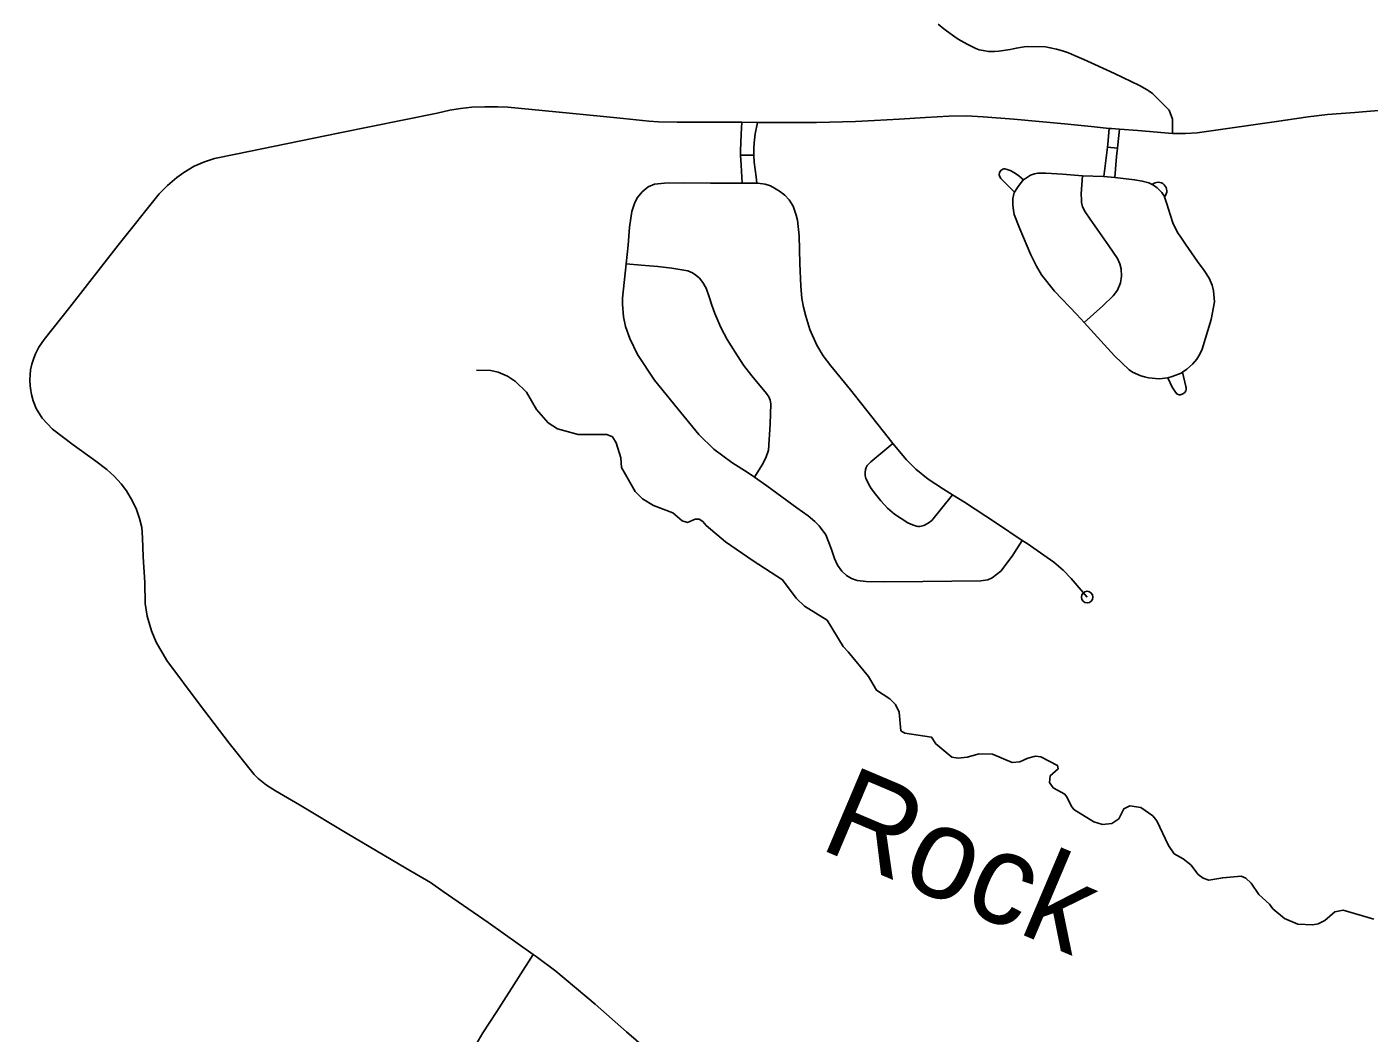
# Model space of a CAD drawing. Extents: x -19 to 366, y -4 to 359.
# Drawn here: x 142.275 to 143.458, y 193.183 to 194.069 of the extents above; entities that cross this region are included whole.
import ezdxf

# ---------------------------------------------------------------- set-up
doc = ezdxf.new("R2010")
doc.units = 0
for name, color, linetype in [('Level 32', 7, 'Continuous'), ('Level 33', 7, 'Continuous'), ('Level 34', 7, 'Continuous'), ('Level 35', 7, 'Continuous'), ('Level 60', 7, 'Continuous')]:
    doc.layers.add(name, color=color, linetype=linetype)

msp = doc.modelspace()

# ---------------------------------------------------------------- linework, layer by layer
at = {"layer": 'Level 32'}
msp.add_lwpolyline([(143.2733, 194.0043), (143.2725, 194.0053), (143.2699, 194.008), (143.2671, 194.0104), (143.2642, 194.0126), (143.2624, 194.0137), (143.2556, 194.0177), (143.2336, 194.0281), (143.2162, 194.0361), (143.2066, 194.0405), (143.1985, 194.0441), (143.1932, 194.0462), (143.1879, 194.048), (143.1825, 194.0496), (143.177, 194.0508), (143.173, 194.0516), (143.1569, 194.052), (143.1541, 194.0516), (143.1506, 194.0511), (143.1473, 194.0505), (143.1445, 194.0499), (143.1418, 194.0493), (143.1319, 194.0477), (143.1279, 194.0475), (143.1228, 194.0475), (143.1181, 194.0483), (143.1145, 194.0491), (143.1115, 194.0501), (143.1067, 194.0524), (143.104, 194.0539), (143.0959, 194.0585), (143.0929, 194.0604), (143.0857, 194.0658), (143.0834, 194.0675), (143.0782, 194.0717)], dxfattribs=at)
at = {"layer": 'Level 33'}
for p, q in [((142.9043, 193.9562), (142.9159, 193.9562)), ((143.2276, 193.9633), (143.2364, 193.9625)), ((142.8034, 193.8604), (142.8052, 193.8768)), ((142.8001, 193.8303), (142.8034, 193.8604)), ((143.0189, 193.686), (143.0385, 193.7023)), ((143.0727, 193.6344), (143.091, 193.657))]:
    msp.add_line(p, q, dxfattribs=at)
for points in [[(143.2848, 193.9752), (143.2962, 193.9752), (143.3065, 193.976), (143.3764, 193.9858), (143.4042, 193.99), (143.4212, 193.9921), (143.4455, 193.9938), (143.4694, 193.9957), (143.4884, 193.9971), (143.5084, 193.9987), (143.5217, 194.0017), (143.5469, 194.0079), (143.5711, 194.0132), (143.5843, 194.0154), (143.5968, 194.0164), (143.608, 194.0172), (143.6204, 194.0177), (143.6361, 194.0167), (143.6637, 194.0127), (143.6699, 194.0116)], [(142.8853, 193.9853), (142.8485, 193.9854), (142.8319, 193.9855), (142.8233, 193.9862), (142.8012, 193.9885), (142.7835, 193.9903), (142.7414, 193.9943), (142.6992, 193.9984), (142.6904, 193.9987), (142.6789, 193.9988), (142.6674, 193.9985), (142.6576, 193.9973), (142.648, 193.9957), (142.6368, 193.9933), (142.5498, 193.9755), (142.4595, 193.9572), (142.4406, 193.9532), (142.4319, 193.9503), (142.4229, 193.9464), (142.4136, 193.941), (142.4074, 193.9364), (142.3993, 193.9295), (142.3919, 193.9221), (142.3559, 193.8769), (142.3133, 193.8223), (142.2906, 193.7937), (142.286, 193.7872), (142.2829, 193.7812), (142.2816, 193.7773), (142.2797, 193.772), (142.2787, 193.7672), (142.2782, 193.7626), (142.278, 193.758), (142.2782, 193.7529), (142.2788, 193.749), (142.2795, 193.7453), (142.2811, 193.7397), (142.2836, 193.7329), (142.2888, 193.7246), (142.2981, 193.7148), (142.3163, 193.7011), (142.3361, 193.6865), (142.3459, 193.6792), (142.3524, 193.6733), (142.3584, 193.6667), (142.3631, 193.6604), (142.3686, 193.6513), (142.3719, 193.6441), (142.3746, 193.6362), (142.3766, 193.6281), (142.3774, 193.6191), (142.378, 193.6025), (142.3792, 193.5799), (142.3797, 193.5612), (142.3814, 193.5502), (142.3853, 193.5371), (142.3893, 193.5271), (142.3987, 193.511), (142.4273, 193.4728), (142.4537, 193.4383), (142.4756, 193.4106), (142.4793, 193.407), (142.4865, 193.4013), (142.4945, 193.3961), (142.5156, 193.3838), (142.5575, 193.3588), (142.6092, 193.3282), (142.6309, 193.3154), (142.6423, 193.3076), (142.6817, 193.2803), (142.7216, 193.2522)], [(143.1895, 193.9838), (143.1674, 193.9857), (143.145, 193.9878), (143.1181, 193.9901), (143.103, 193.9907), (143.0878, 193.9905), (143.0671, 193.9895), (143.0439, 193.9878), (143.0222, 193.9867), (143.0055, 193.9858), (142.9711, 193.9849), (142.919, 193.9851)], [(142.9054, 193.9852), (142.8853, 193.9853)], [(142.9043, 193.9562), (142.9041, 193.9601), (142.9046, 193.9746), (142.9054, 193.9852)], [(142.919, 193.9851), (142.9054, 193.9852)], [(142.919, 193.9851), (142.9171, 193.975), (142.9162, 193.9671), (142.916, 193.9621), (142.9159, 193.9562)], [(143.229, 193.9798), (143.2132, 193.9814), (143.1895, 193.9838)], [(143.229, 193.9798), (143.2279, 193.966), (143.2276, 193.9633)], [(143.2381, 193.9791), (143.2311, 193.9796), (143.229, 193.9798)], [(143.2381, 193.9791), (143.2367, 193.9653), (143.2364, 193.9625)], [(143.2849, 193.9752), (143.2542, 193.9778), (143.2381, 193.9791)], [(142.9056, 193.9314), (142.9048, 193.9473), (142.9043, 193.9562)], [(142.9159, 193.9562), (142.9159, 193.9562), (142.9162, 193.95), (142.9179, 193.937), (142.9184, 193.9314)], [(143.2276, 193.9633), (143.2244, 193.9373)], [(143.2364, 193.9625), (143.2355, 193.955), (143.2341, 193.9366)], [(143.1457, 193.9237), (143.1334, 193.9357), (143.1326, 193.9371), (143.1322, 193.9389), (143.1323, 193.9408), (143.1334, 193.9427), (143.1343, 193.9434), (143.1352, 193.944), (143.1361, 193.9442), (143.1371, 193.9442), (143.1391, 193.9437), (143.1418, 193.9428), (143.1456, 193.9405), (143.1493, 193.938), (143.1534, 193.9346)], [(142.8052, 193.8768), (142.8064, 193.8928), (142.8083, 193.9065), (142.811, 193.9145), (142.8135, 193.9188), (142.8174, 193.9238), (142.8227, 193.9282), (142.8285, 193.9305), (142.8373, 193.9314), (142.8542, 193.9319), (142.8777, 193.9314), (142.9056, 193.9314)], [(142.9056, 193.9314), (142.9184, 193.9314)], [(142.9184, 193.9314), (142.9193, 193.9314), (142.9258, 193.9306), (142.9305, 193.9291), (142.9341, 193.9272), (142.9385, 193.9244), (142.9431, 193.9209), (142.947, 193.9168), (142.9505, 193.9113), (142.9532, 193.9033), (142.9545, 193.899), (142.9557, 193.885), (142.9565, 193.8608), (142.9573, 193.8409), (142.9582, 193.83), (142.9597, 193.8223), (142.9618, 193.8143), (142.9653, 193.8027), (142.9713, 193.7887), (142.9769, 193.7795), (142.9836, 193.7706), (143.0012, 193.7496), (143.0343, 193.7074), (143.0385, 193.7023)], [(143.1457, 193.9237), (143.1481, 193.9278), (143.1532, 193.9345), (143.1534, 193.9346)], [(143.1534, 193.9346), (143.1596, 193.9386), (143.1631, 193.9396), (143.1662, 193.9402), (143.1732, 193.9403), (143.1878, 193.9395)], [(143.1878, 193.9395), (143.2054, 193.9381)], [(143.2068, 193.8089), (143.2234, 193.8236), (143.2326, 193.8322), (143.2364, 193.8373), (143.2389, 193.8437), (143.2399, 193.8495), (143.2396, 193.856), (143.2385, 193.8605), (143.2362, 193.8652), (143.2287, 193.8762), (143.2122, 193.8997), (143.2078, 193.9063), (143.2056, 193.9107), (143.2047, 193.9146), (143.2045, 193.9168), (143.2044, 193.922), (143.2054, 193.9381)], [(143.2054, 193.9381), (143.2241, 193.9373), (143.2244, 193.9373)], [(143.2244, 193.9373), (143.2341, 193.9366)], [(143.2341, 193.9366), (143.2514, 193.9345), (143.2581, 193.9333), (143.2639, 193.9317), (143.2669, 193.9304)], [(143.1504, 193.8913), (143.1453, 193.9039), (143.1446, 193.9077), (143.144, 193.912), (143.1442, 193.9181), (143.1453, 193.9232), (143.1457, 193.9237)], [(143.2669, 193.9304), (143.268, 193.9299), (143.2714, 193.9275), (143.2753, 193.9234), (143.2778, 193.9197), (143.2778, 193.9196)], [(143.2778, 193.9196), (143.2799, 193.9132), (143.2826, 193.9039), (143.2855, 193.8957), (143.2899, 193.8872), (143.2914, 193.8847)], [(143.2068, 193.8089), (143.2004, 193.8159), (143.1808, 193.8365), (143.1693, 193.8509), (143.165, 193.8585), (143.1601, 193.8683), (143.1504, 193.8913)], [(143.3219, 193.827), (143.321, 193.8366), (143.3196, 193.8418), (143.317, 193.8478), (143.3127, 193.8546), (143.3069, 193.8624), (143.2961, 193.8777), (143.2914, 193.8847)], [(142.9164, 193.6725), (142.9233, 193.6833), (142.9266, 193.6896), (142.9289, 193.6962), (142.9303, 193.7191), (142.931, 193.7372), (142.9304, 193.7405), (142.9291, 193.7434), (142.9271, 193.7463), (142.914, 193.7617), (142.9068, 193.7711), (142.8995, 193.7827), (142.8924, 193.7938), (142.8867, 193.8044), (142.8815, 193.8168), (142.8789, 193.8241), (142.8765, 193.8315), (142.8739, 193.8391), (142.871, 193.8439), (142.8679, 193.8479), (142.8649, 193.8505), (142.8618, 193.8526), (142.8577, 193.8542), (142.8526, 193.8553), (142.8436, 193.8567), (142.8312, 193.8581), (142.8166, 193.8592), (142.8034, 193.8604)], [(142.8001, 193.8303), (142.8003, 193.8249), (142.8012, 193.8139), (142.8029, 193.8053), (142.8066, 193.7948), (142.8133, 193.7807), (142.8284, 193.7581), (142.8489, 193.7327), (142.8675, 193.7101), (142.8808, 193.6972), (142.8966, 193.6855), (142.911, 193.6763), (142.9164, 193.6725)], [(143.3219, 193.827), (143.3187, 193.8115), (143.3108, 193.7854), (143.309, 193.7809), (143.3061, 193.7766), (143.3024, 193.7722), (143.2975, 193.7677), (143.2936, 193.7651)], [(143.2466, 193.7672), (143.2338, 193.7793), (143.2216, 193.7927), (143.2068, 193.8089)], [(143.2808, 193.76), (143.2807, 193.76), (143.273, 193.7592), (143.2637, 193.7599), (143.2601, 193.7608), (143.257, 193.7617), (143.2496, 193.7651), (143.2466, 193.7672)], [(143.2936, 193.7651), (143.2923, 193.7642), (143.2844, 193.7611), (143.2808, 193.76)], [(143.2808, 193.76), (143.2846, 193.7518), (143.2873, 193.7474), (143.2885, 193.7459), (143.2892, 193.7456), (143.2906, 193.7452), (143.2918, 193.7452), (143.294, 193.746), (143.2957, 193.7472), (143.2966, 193.7485), (143.2969, 193.7497), (143.2968, 193.7514), (143.2966, 193.7523), (143.2936, 193.7651)], [(143.0385, 193.7023), (143.0505, 193.6878), (143.0585, 193.6797), (143.0696, 193.6709), (143.0831, 193.662), (143.091, 193.657)], [(143.0189, 193.686), (143.0159, 193.6828), (143.015, 193.6811), (143.0143, 193.6792), (143.014, 193.6766), (143.0141, 193.6739), (143.0147, 193.6713), (143.0157, 193.6692), (143.0171, 193.6662), (143.0194, 193.6625), (143.023, 193.6575), (143.0279, 193.6516), (143.0337, 193.6451), (143.0397, 193.6399), (143.0456, 193.6361), (143.0515, 193.6324), (143.0556, 193.6305), (143.0591, 193.6293), (143.0605, 193.6292), (143.0618, 193.6292), (143.0632, 193.6294), (143.0656, 193.63), (143.0696, 193.6319), (143.0727, 193.6344)], [(142.9164, 193.6725), (142.9274, 193.6648), (142.9539, 193.6456), (142.9637, 193.6384), (142.9697, 193.6335), (142.9734, 193.6298), (142.9792, 193.6217), (142.9821, 193.615), (142.9843, 193.6088), (142.987, 193.601), (142.9896, 193.595), (142.9933, 193.5898), (142.9976, 193.5858), (143.0019, 193.5832), (143.0068, 193.5816), (143.0148, 193.5805), (143.0307, 193.5803), (143.0647, 193.5806), (143.1158, 193.5812), (143.1221, 193.5821), (143.126, 193.5839), (143.1336, 193.5897), (143.1434, 193.603), (143.1523, 193.6168)], [(143.091, 193.657), (143.1014, 193.6504), (143.1296, 193.632), (143.1523, 193.6168)], [(143.1523, 193.6168), (143.1566, 193.614), (143.1802, 193.5978)], [(143.2097, 193.5668), (143.2043, 193.5731), (143.1954, 193.5833), (143.1883, 193.5907), (143.1802, 193.5978)], [(142.6048, 193.0965), (142.609, 193.103), (142.6124, 193.1081), (142.6163, 193.1142), (142.6192, 193.1185), (142.6246, 193.124), (142.6429, 193.141), (142.6552, 193.1521), (142.662, 193.1591), (142.6664, 193.1646), (142.6729, 193.176), (142.6771, 193.1831), (142.6895, 193.202), (142.7087, 193.2319), (142.7216, 193.2522)], [(142.7216, 193.2522), (142.7242, 193.2504), (142.7414, 193.2374), (142.776, 193.2082), (142.8037, 193.184), (142.8313, 193.1601)]]:
    msp.add_lwpolyline(points, dxfattribs=at)
msp.add_circle((143.2096, 193.5669), 0.00509, dxfattribs=at)
msp.add_arc((143.2721, 193.9247), 0.00765, 318.0474, 132.7124, dxfattribs=at)
at = {"layer": 'Level 34'}
msp.add_lwpolyline([(143.2848, 193.9752), (143.2848, 193.988), (143.2818, 193.9959), (143.2733, 194.0043)], dxfattribs=at)
at = {"layer": 'Level 35'}
for points in [[(142.8677, 193.6356), (142.8643, 193.6356), (142.8575, 193.6327), (142.8529, 193.6342), (142.8445, 193.6411), (142.8274, 193.6476), (142.8179, 193.6534), (142.8114, 193.66), (142.7993, 193.6811), (142.7986, 193.6896), (142.7947, 193.7027), (142.7913, 193.7082), (142.7863, 193.71), (142.7611, 193.71), (142.7429, 193.7152), (142.7347, 193.7204), (142.7244, 193.7321), (142.7155, 193.7474), (142.706, 193.7568), (142.6989, 193.7615), (142.6907, 193.765), (142.6841, 193.7666), (142.6716, 193.7667)], [(143.3074, 193.3226), (143.3008, 193.331), (143.2943, 193.3363), (143.2863, 193.3408), (143.2812, 193.3481), (143.2711, 193.3697), (143.2675, 193.3742), (143.257, 193.3815), (143.2473, 193.3831), (143.242, 193.3804), (143.2374, 193.3715), (143.2312, 193.3676), (143.2232, 193.3666), (143.2154, 193.369), (143.1979, 193.3799), (143.1954, 193.3829), (143.1921, 193.3904), (143.1898, 193.3933), (143.1795, 193.3989), (143.1763, 193.4036), (143.177, 193.4095), (143.1839, 193.4156), (143.1834, 193.4186), (143.1687, 193.4261), (143.1641, 193.4268), (143.1573, 193.425), (143.1502, 193.4218), (143.1435, 193.4213), (143.1262, 193.4284), (143.1145, 193.4287), (143.1039, 193.4259), (143.096, 193.4249), (143.0904, 193.426), (143.0763, 193.4375), (143.0725, 193.4435), (143.0488, 193.4469), (143.0453, 193.4491), (143.0439, 193.4654), (143.0406, 193.4722), (143.0358, 193.4773), (143.024, 193.4848), (143.0169, 193.4969), (142.9989, 193.5187), (142.9945, 193.5233), (142.9806, 193.5465), (142.9606, 193.559), (142.9532, 193.5661), (142.9411, 193.5822), (142.9154, 193.5988), (142.8908, 193.6155), (142.874, 193.63), (142.8711, 193.6334), (142.8677, 193.6356)], [(143.4621, 193.2833), (143.4351, 193.291), (143.4278, 193.2896), (143.4191, 193.2821), (143.4131, 193.2791), (143.4083, 193.2783), (143.3951, 193.2789), (143.3835, 193.2837), (143.3732, 193.2922), (143.3703, 193.2963), (143.3607, 193.305), (143.3542, 193.3148), (143.3493, 193.3193), (143.3453, 193.321), (143.329, 193.3197), (143.3167, 193.3175), (143.3117, 193.3192), (143.3074, 193.3226)]]:
    msp.add_lwpolyline(points, dxfattribs=at)
at = {"layer": 'Level 60'}
for points in [[(146.7783, 1.697), (146.5788, 10.3131), (146.3785, 18.9294), (146.1776, 27.5458), (145.9759, 36.1624), (145.7736, 44.7791), (145.5705, 53.396), (145.3668, 62.013), (145.1624, 70.6301), (144.9572, 79.2474), (144.7514, 87.8648), (144.5449, 96.4823), (144.3377, 105.1), (144.1299, 113.7179), (143.9213, 122.3359), (143.712, 130.954), (143.5021, 139.5723), (143.2915, 148.1907), (143.0802, 156.8092), (142.8682, 165.4279), (142.6555, 174.0468), (142.4422, 182.6658), (142.2282, 191.2849), (142.0135, 199.9042), (141.7981, 208.5236), (141.582, 217.1432), (141.3653, 225.7629), (141.1479, 234.3828), (140.9298, 243.0028), (140.711, 251.623), (140.4916, 260.2433), (140.2715, 268.8638), (140.0508, 277.4844), (139.8293, 286.1051), (139.6072, 294.726), (139.3845, 303.3471), (139.161, 311.9683), (138.937, 320.5896), (138.7122, 329.2111), (138.4868, 337.8328), (138.2607, 346.4546)], [(0, 189.5162), (7.1121, 189.5206), (14.2243, 189.5339), (21.3364, 189.556), (28.4484, 189.5869), (35.5605, 189.6267), (42.6725, 189.6754), (49.7844, 189.7329), (56.8962, 189.7992), (64.0079, 189.8744), (71.1196, 189.9584), (78.2311, 190.0512), (85.3425, 190.1529), (92.4538, 190.2635), (99.5649, 190.3829), (106.6759, 190.5111), (113.7867, 190.6482), (120.8974, 190.7941), (128.0078, 190.9489), (135.1181, 191.1125), (142.2282, 191.2849), (149.338, 191.4662), (156.4476, 191.6563), (163.5569, 191.8553), (170.666, 192.0631), (177.7749, 192.2798), (184.8835, 192.5053), (191.9917, 192.7396), (199.0997, 192.9828), (206.2074, 193.2348), (213.3147, 193.4956), (220.4218, 193.7653), (227.5285, 194.0438), (234.6348, 194.3312), (241.7408, 194.6274), (248.8464, 194.9324), (255.9516, 195.2463), (263.0564, 195.569), (270.1608, 195.9005), (277.2648, 196.2409), (284.3683, 196.5901), (291.4715, 196.9481), (298.5741, 197.315), (305.6763, 197.6907), (312.7781, 198.0753), (319.8793, 198.4686), (326.9801, 198.8708), (334.0804, 199.2818), (341.1801, 199.7017)]]:
    msp.add_spline(points, degree=3, dxfattribs=at)

# ---------------------------------------------------------------- texts
at = {"layer": 'Level 35'}
msp.add_text('Rock', height=0.08, rotation=337.0448, dxfattribs=at).set_placement((142.972, 193.3459))

doc.saveas('drawing.dxf')
